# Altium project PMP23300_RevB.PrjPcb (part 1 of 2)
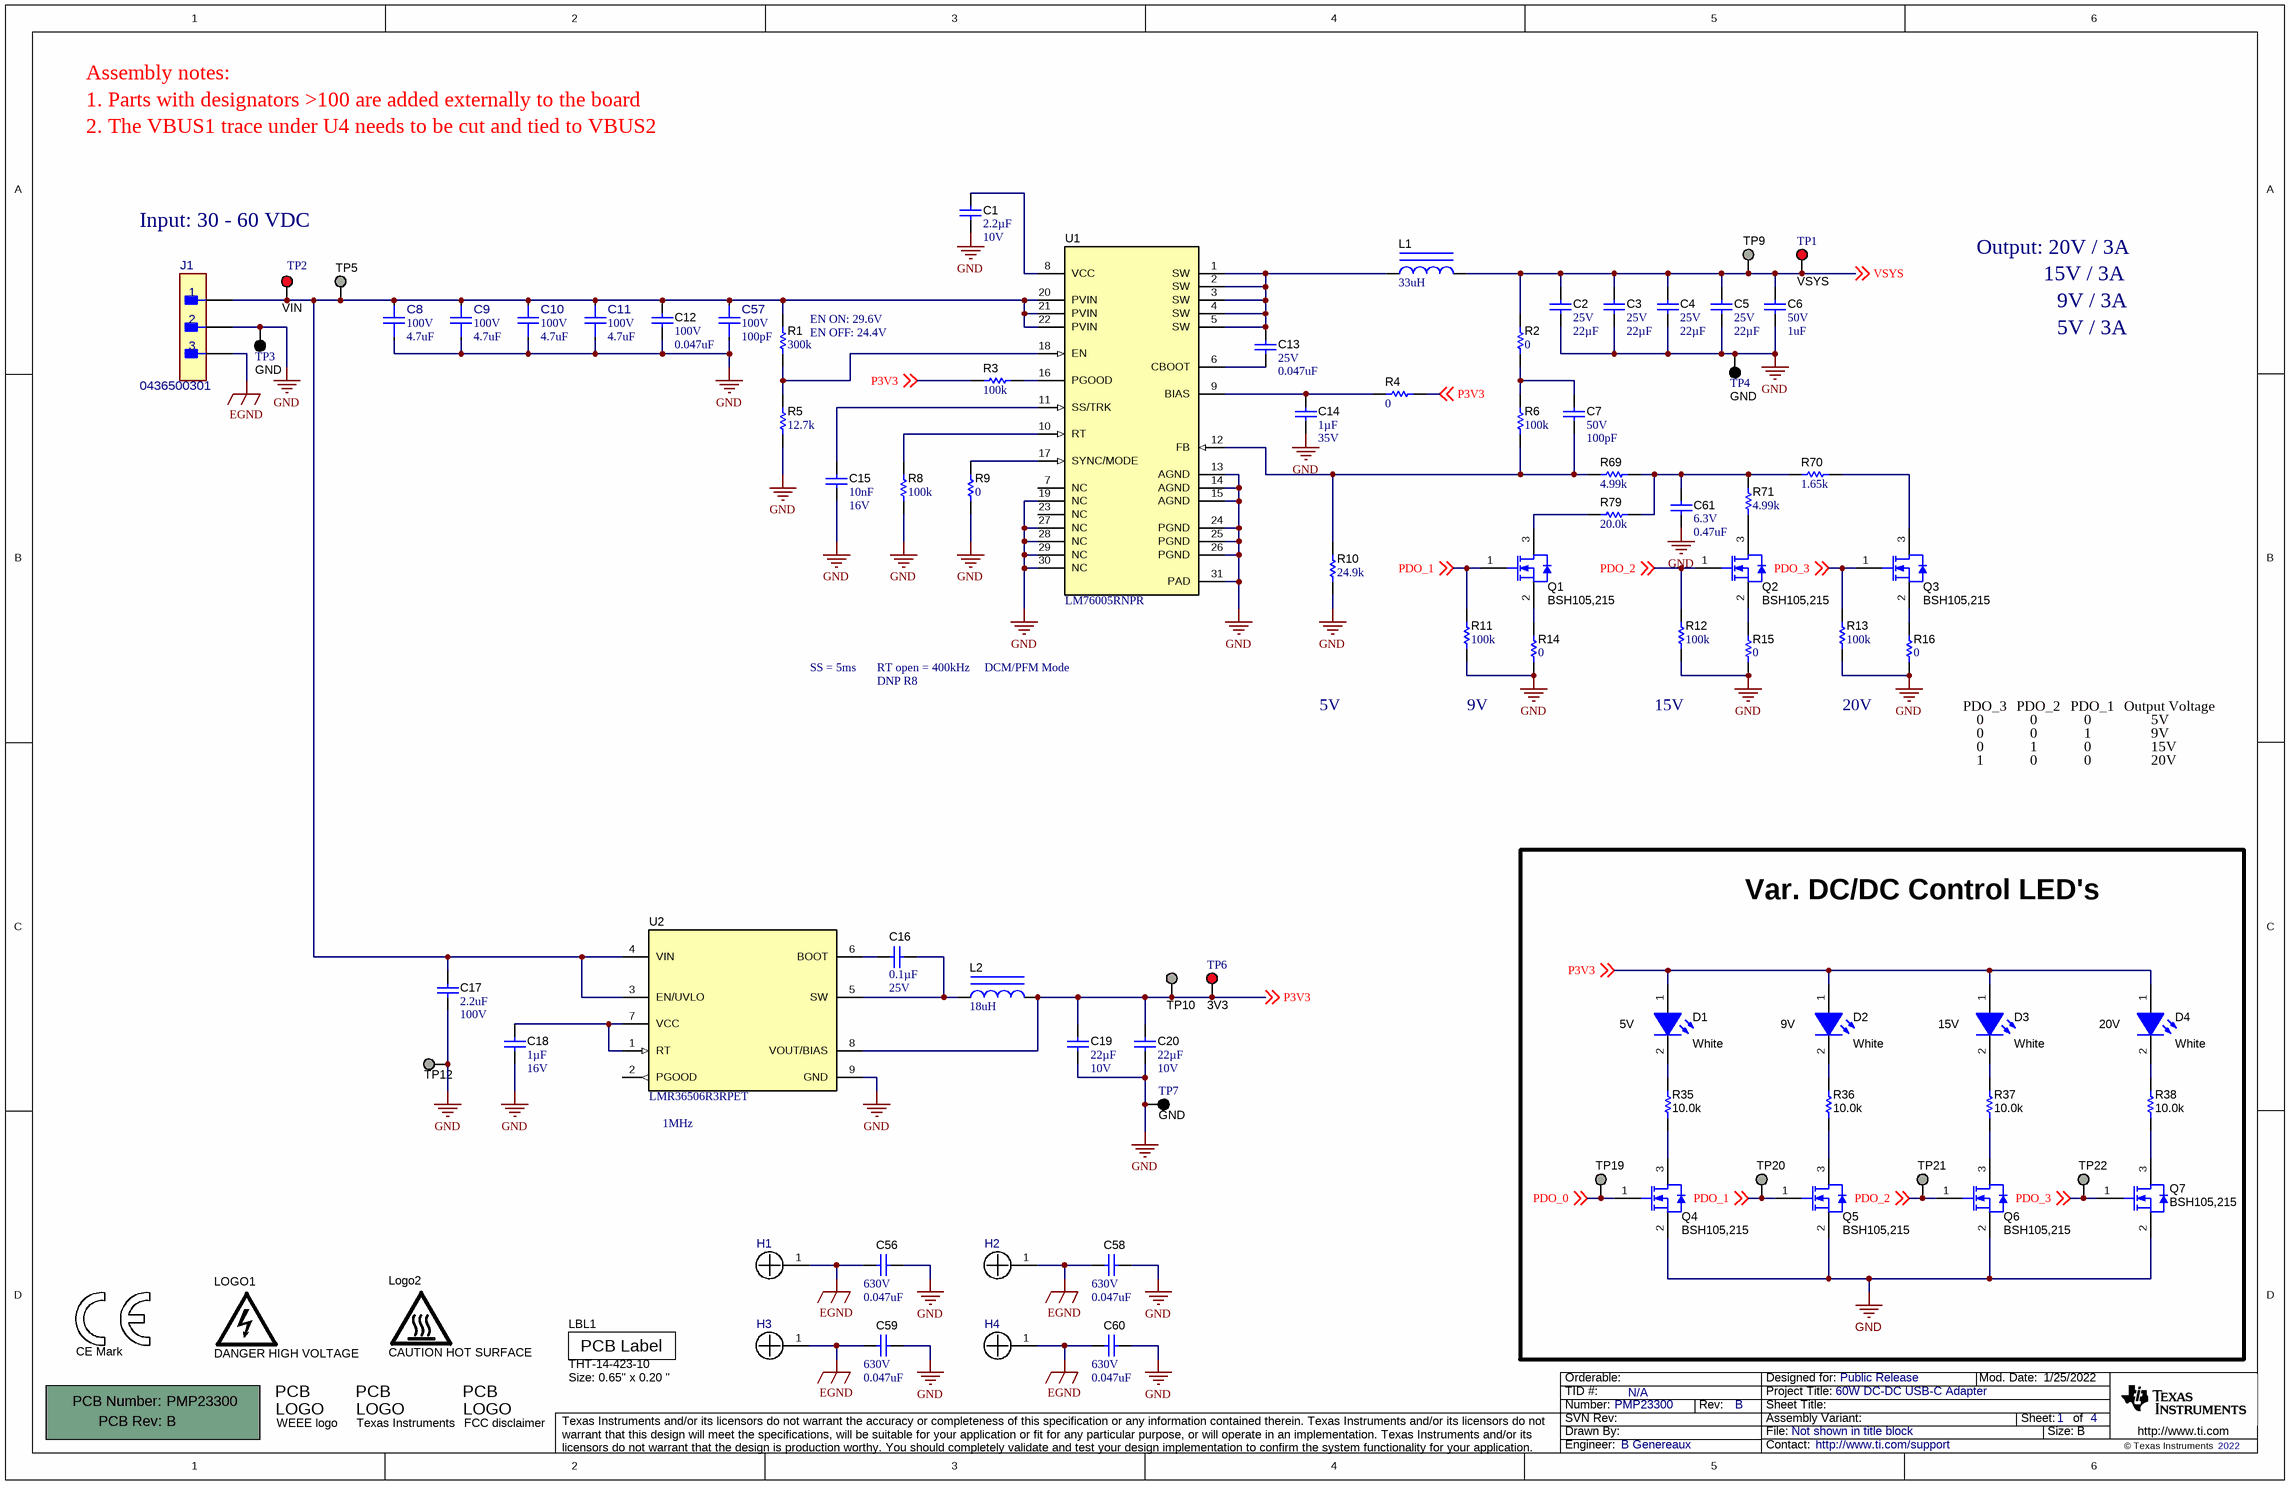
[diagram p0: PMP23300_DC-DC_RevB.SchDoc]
CopyrightYear: 2022; PCB_Rev: B; PRJ_Customer: Public Release; PRJ_Engineer: B Genereaux; PRJ_Number: PMP23300; PRJ_Title: 60W DC-DC USB-C Adapter; SCH_Rev: B; TechSupport: http://www.ti.com/support; TID: N/A
4 sheets, 204 parts. Net scope: global (net labels, ports and power ports of the same name join across sheets).
Board file: PMP23300_RevB.PcbDoc
Sheets:
  PMP23300_DC-DC_RevB.SchDoc
  PMP23300_PD_Control_RevB.SchDoc
  PMP23300_TIVA_RevB.SchDoc
  PMP23300_PD_Power_RevB.SchDoc

## Sheet PMP23300_DC-DC_RevB.SchDoc
size 431 x 279 mm; Date: Not shown in title block; ApprovedBy: Not shown in title block; CheckedBy: Not shown in title block; Author: Not shown in title block; CompanyName: Not shown in title block; Engineer: Not shown in title block; Organization: Not shown in title block; Address1: Not shown in title block; Address2: Not shown in title block; Address3: Not shown in title block; Address4: Not shown in title block; DocumentNumber: 1; Revision: Use project parameter SCH_Rev; SheetNumber: 1; SheetTotal: 4; PageSetup: Record=PageOptions¦CenterHorizontal=True¦CenterVertical=True¦PrintScale=1.00¦XCorrection=1.00¦YCorrection=1.00¦PrintKind=0¦BorderSize=5000000¦LeftOffset=0¦BottomOffset=0¦Orientation=2¦PaperLength=1000¦PaperWidth=1000¦Scale=100¦PaperSource=15¦PrintQuality=600¦MediaType=1¦DitherType=10¦PaperKind=Letter¦PrintScaleMode=1

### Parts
!PCB1  Printed Circuit Board  (value not drawn)  (mechanical)
C1  Cap_F: 2.2µF  VDC_V: 10V  [0603]  (hidden comment: GRM188R71A225KE15D)
C2  VDC_V: 25V  ValueDisplayed: 22µF  [1210_280]  (hidden comment: C1210C226K3RAC7800)
C3  VDC_V: 25V  ValueDisplayed: 22µF  [1210_280]  (hidden comment: C1210C226K3RAC7800)
C4  VDC_V: 25V  ValueDisplayed: 22µF  [1210_280]  (hidden comment: C1210C226K3RAC7800)
C5  VDC_V: 25V  ValueDisplayed: 22µF  [1210_280]  (hidden comment: C1210C226K3RAC7800)
C6  VDC_V: 50V  ValueDisplayed: 1uF  [0603]  (hidden comment: C1608X5R1H105K080AB)
C7  VDC_V: 50V  ValueDisplayed: 100pF  [0402]  (hidden comment: 04025A101FAT2A)
C8  VDC_V: 100V  ValueDisplayed: 4.7uF  [FP-CNC6P1X7R2A475K250AE_1210-MFG]  (hidden comment: CNC6P1X7R2A475K250AE)
C9  VDC_V: 100V  ValueDisplayed: 4.7uF  [FP-CNC6P1X7R2A475K250AE_1210-MFG]  (hidden comment: CNC6P1X7R2A475K250AE)
C10  VDC_V: 100V  ValueDisplayed: 4.7uF  [FP-CNC6P1X7R2A475K250AE_1210-MFG]  (hidden comment: CNC6P1X7R2A475K250AE)
C11  VDC_V: 100V  ValueDisplayed: 4.7uF  [FP-CNC6P1X7R2A475K250AE_1210-MFG]  (hidden comment: CNC6P1X7R2A475K250AE)
C12  VDC_V: 100V  ValueDisplayed: 0.047uF  [0603]  (hidden comment: C1608X7S2A473K080AB)
C13  VDC_V: 25V  ValueDisplayed: 0.047uF  [0402]  (hidden comment: GRM155R71E473KA88D)
C14  Cap_F: 1µF  VDC_V: 35V  [0603]  (hidden comment: C1608X7R1V105K080AC)
C15  Cap_F: 10nF  VDC_V: 16V  [0603]  (hidden comment: GRM188R71C103KA01D)
C16  ValueDisplayed: 0.1µF  VDC_V: 25V  [0402]  (hidden comment: CC0402KRX7R8BB104)
C17  ValueDisplayed: 2.2uF  VDC_V: 100V  [1206_190]  (hidden comment: GRM31CR72A225KA73L)
C18  Cap_F: 1µF  VDC_V: 16V  [0603]  (hidden comment: CL10B105KO8NFNC)
C19  Cap_F: 22µF  VDC_V: 10V  [0805_HV]  (hidden comment: GRM21BZ71A226ME15L)
C20  Cap_F: 22µF  VDC_V: 10V  [0805_HV]  (hidden comment: GRM21BZ71A226ME15L)
C56  VDC_V: 630V  ValueDisplayed: 0.047uF  [1206]
C57  VDC_V: 100V  Cap_F: 100pF  [FP-06031C101JAT2A_0603-MFG]  (hidden comment: 06031C101JAT2A)
C58  VDC_V: 630V  ValueDisplayed: 0.047uF  [1206]
C59  VDC_V: 630V  ValueDisplayed: 0.047uF  [1206]
C60  VDC_V: 630V  ValueDisplayed: 0.047uF  [1206]
C61  VDC_V: 6.3V  ValueDisplayed: 0.47uF  [0402]  (hidden comment: JMK105B7474KVHF)
D1  value White  [LW QH8G_White]  (hidden comment: LW QH8G-Q2S2-3K5L-1)
D2  value White  [LW QH8G_White]  (hidden comment: LW QH8G-Q2S2-3K5L-1)
D3  value White  [LW QH8G_White]  (hidden comment: LW QH8G-Q2S2-3K5L-1)
D4  value White  [LW QH8G_White]  (hidden comment: LW QH8G-Q2S2-3K5L-1)
H1  NY PMS 440 0025 PH  [NY PMS 440 0025 PH]  (value not drawn)
H2  NY PMS 440 0025 PH  [NY PMS 440 0025 PH]  (value not drawn)
H3  NY PMS 440 0025 PH  [NY PMS 440 0025 PH]  (value not drawn)
H4  NY PMS 440 0025 PH  [NY PMS 440 0025 PH]  (value not drawn)
J1  0436500301  [FP-0436500301_CONN_HDR3-MFG]
L1  ValueDisplayed: 33uH  [WE-PD_1210]  (hidden comment: 7447709330)
L2  ValueDisplayed: 18uH  [WE-TPC-LH]  (hidden comment: 744053180)
LBL1  THT-14-423-10  Note: Size: 0.65" x 0.20 "  [Label_650x200]
LOGO1  DANGER HIGH VOLTAGE  [IEC_HighVoltage_Small]  (no BOM)
Logo2  CAUTION HOT SURFACE  [IEC_HotSurface_Small]  (no BOM)
Logo3  CE Mark  [CE_Mark_5mm]  (no BOM)
Logo4  WEEE logo  [WEEE_Minimum]  (no BOM)
Logo5  Texas Instruments  [TI_Stacked_Overlay_Small]  (no BOM)
Logo6  FCC disclaimer  [FCC_disclaimer]  (no BOM)
Q1  BSH105,215  [SOT-23]
Q2  BSH105,215  [SOT-23]
Q3  BSH105,215  [SOT-23]
Q4  BSH105,215  [SOT-23]
Q5  BSH105,215  [SOT-23]
Q6  BSH105,215  [SOT-23]
Q7  BSH105,215  [SOT-23]
R1  ValueDisplayed: 300k  [0402]  (hidden comment: CRCW0402300KFKED)
R2  ValueDisplayed: 0  [0402]  (hidden comment: CRCW04020000Z0EDHP)
R3  ValueDisplayed: 100k  [0402]  (hidden comment: RC1005F104CS)
R4  ValueDisplayed: 0  [0402]  (hidden comment: CRCW04020000Z0EDHP)
R5  ValueDisplayed: 12.7k  [0402]  (hidden comment: CRCW040212K7FKED)
R6  ValueDisplayed: 100k  [0402]  (hidden comment: RC1005F104CS)
R8  ValueDisplayed: 100k  [0402]  (hidden comment: RC1005F104CS)
R9  ValueDisplayed: 0  [0402]  (hidden comment: CRCW04020000Z0EDHP)
R10  ValueDisplayed: 24.9k  [0402]  (hidden comment: CRCW040224K9FKED)
R11  ValueDisplayed: 100k  [0402]  (hidden comment: RC1005F104CS)
R12  ValueDisplayed: 100k  [0402]  (hidden comment: RC1005F104CS)
R13  ValueDisplayed: 100k  [0402]  (hidden comment: RC1005F104CS)
R14  ValueDisplayed: 0  [0402]  (hidden comment: CRCW04020000Z0EDHP)
R15  ValueDisplayed: 0  [0402]  (hidden comment: CRCW04020000Z0EDHP)
R16  ValueDisplayed: 0  [0402]  (hidden comment: CRCW04020000Z0EDHP)
R35  ValueDisplayed: 10.0k  [0402]  (hidden comment: ERJ-2RKF1002X)
R36  ValueDisplayed: 10.0k  [0402]  (hidden comment: ERJ-2RKF1002X)
R37  ValueDisplayed: 10.0k  [0402]  (hidden comment: ERJ-2RKF1002X)
R38  ValueDisplayed: 10.0k  [0402]  (hidden comment: ERJ-2RKF1002X)
R69  ValueDisplayed: 4.99k  [0402]  (hidden comment: RC0402FR-074K99L)
R70  ValueDisplayed: 1.65k  [0402]  (hidden comment: CRCW04021K65FKED)
R71  ValueDisplayed: 4.99k  [0402]  (hidden comment: RC0402FR-074K99L)
R79  ValueDisplayed: 20.0k  [0402]  (hidden comment: CRCW040220K0FKED)
TP1  VSYS  [Keystone5010]
TP2  VIN  [Keystone5010]
TP3  GND  [Keystone5011]
TP4  GND  [Keystone5011]
TP5  S1751-46  [Harwin_S1751-46]  (value not drawn)
TP6  3V3  [Keystone5010]
TP7  GND  [Keystone5011]
TP9  S1751-46  [Harwin_S1751-46]  (value not drawn)
TP10  S1751-46  [Harwin_S1751-46]  (value not drawn)
TP12  S1751-46  [Harwin_S1751-46]  (value not drawn)
TP19  S1751-46  [Harwin_S1751-46]  (value not drawn)
TP20  S1751-46  [Harwin_S1751-46]  (value not drawn)
TP21  S1751-46  [Harwin_S1751-46]  (value not drawn)
TP22  S1751-46  [Harwin_S1751-46]  (value not drawn)
U1  LM76005RNPR  [RNP0030A]
U2  LMR36506R3RPET  [RPE0009A]

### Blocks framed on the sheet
Var. DC/DC Control LED's: D1-D4 Q4-Q7 R35-R38 TP19-TP22

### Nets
EGND: C56.2 C58.2 C59.2 C60.2 H1.1 H2.1 H3.1 H4.1 J1.3
GND: C1.2 C2.2 C3.2 C4.2 C5.2 C6.2 C8.1 C9.1 C10.1 C11.1 C12.2 C14.2 C15.2 C17.2 C18.2 C19.2 C20.2 C56.1 C57.1 C58.1 C59.1 C60.1 C61.2 J1.2 Q4.2(S) Q5.2(S) Q6.2(S) Q7.2(S) R5.1 R8.1 R9.2 R10.1 R11.1 R12.1 R13.1 R14.2 R15.2 R16.2 TP3.1 TP4.1 TP7.1 TP12.1 U1.13(AGND) U1.14(AGND) U1.15(AGND) U1.19(NC) U1.24(PGND) U1.25(PGND) U1.26(PGND) U1.27(NC) U1.28(NC) U1.29(NC) U1.30(NC) U1.31(PAD) U2.9(GND)
P3V3: C19.1 C20.1 D1.1(A) D2.1(A) D3.1(A) D4.1(A) L2.2 R3.1 R4.1 TP6.1 TP10.1 U2.8(VOUT/BIAS) ; off-sheet P3V3
PDO_0: Q4.1(G) TP19.1 ; off-sheet PDO_0
PDO_1: Q1.1(G) Q5.1(G) R11.2 TP20.1 ; off-sheet PDO_1
PDO_2: Q2.1(G) Q6.1(G) R12.2 TP21.1 ; off-sheet PDO_2
PDO_3: Q3.1(G) Q7.1(G) R13.2 TP22.1 ; off-sheet PDO_3
VSYS: C2.1 C3.1 C4.1 C5.1 C6.1 L1.2 R2.1 TP1.1 TP9.1 ; off-sheet VSYS
NetC1_1: C1.1 U1.8(VCC)
NetC7_1: C7.1 R2.2 R6.2
NetC7_2: C7.2 R6.1 R10.2 R69.1 U1.12(FB)
NetC8_2: C8.2 C9.2 C10.2 C11.2 C12.1 C17.1 C57.2 J1.1 R1.2 TP2.1 TP5.1 U1.20(PVIN) U1.21(PVIN) U1.22(PVIN) U2.3(EN/UVLO) U2.4(VIN)
NetC13_1: C13.1 L1.1 U1.1(SW) U1.2(SW) U1.3(SW) U1.4(SW) U1.5(SW)
NetC13_2: C13.2 U1.6(CBOOT)
NetC14_1: C14.1 R4.2 U1.9(BIAS)
NetC15_1: C15.1 U1.11(SS/TRK)
NetC16_1: C16.1 L2.1 U2.5(SW)
NetC16_2: C16.2 U2.6(BOOT)
NetC18_1: C18.1 U2.1(RT) U2.7(VCC)
NetC61_1: C61.1 R69.2 R70.1 R71.2 R79.2
NetD1_2: D1.2(K) R35.2
NetD2_2: D2.2(K) R36.2
NetD3_2: D3.2(K) R37.2
NetD4_2: D4.2(K) R38.2
NetQ1_2: Q1.2(S) R14.1
NetQ1_3: Q1.3(D) R79.1
NetQ2_2: Q2.2(S) R15.1
NetQ2_3: Q2.3(D) R71.1
NetQ3_2: Q3.2(S) R16.1
NetQ3_3: Q3.3(D) R70.2
NetQ4_3: Q4.3(D) R35.1
NetQ5_3: Q5.3(D) R36.1
NetQ6_3: Q6.3(D) R37.1
NetQ7_3: Q7.3(D) R38.1
NetR1_1: R1.1 R5.2 U1.18(EN)
NetR3_2: R3.2 U1.16(PGOOD)
NetR8_2: R8.2 U1.10(RT)
NetR9_1: R9.1 U1.17(SYNC/MODE)

Not connected (* = marked no-connect by the designer): U1 7(NC) 23(NC); U2 2(PGOOD)

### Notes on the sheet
- Assembly notes:
- 1. Parts with designators >100 are added externally to the board
- 2. The VBUS1 trace under U4 needs to be cut and tied to VBUS2
- Input: 30 - 60 VDC
- Output: 20V / 3A
- 15V / 3A
- (near R1) EN ON: 29.6V
- (near R1) EN OFF: 24.4V
- 9V / 3A
- 5V / 3A
- SS = 5ms
- RT open = 400kHz
- DNP R8
- DCM/PFM Mode
- 5V
- 9V
- (near R12) 15V
- 20V
- PDO_3
- 0
- 1
- PDO_2
- PDO_1
- Output Voltage
- 15V
- (near D1) 5V
- (near D2) 9V
- (near D3) 15V
- (near D4) 20V
- (near U2) 1MHz

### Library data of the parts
!PCB1 = CMP-0003618-2: Manufacturer: Any; PartNumber: PMP23300
C1 = CMP-0007370-4: CAP, CERM, 2.2 uF, 10 V, +/- 10%, X7R, 0603; Manufacturer: MuRata; TaMin_C: -55°C; ESR_ohm: 9m; Polarized: N; SizeAreaWB_mm2: 4.68; Value1: 0.009 ohm; U/M: EA; Value: 2.2uF; TaMax_C: 125°C; SizeZ_mm: 1; SizeX_mm: 1.6; SizeY_mm: 0.8; SizeArea_mm2: 1.28; AEC Category: Q200
C2-C5 = CMP-0082266-1: CAP, CERM, 22 µF, 25 V,+/- 10%, X7R, 1210; Manufacturer: Kemet; TaMin_C: -55°C; ESR_ohm: 1m; Polarized: N; Green_Lifecycle: Active; SizeAreaWB_mm2: 14.7; Green_REACh: Incomplete; Value1: 0.001 ohm; U/M: EA; Value: 22uF; TaMax_C: 125°C; SizeZ_mm: 2.8; SizeX_mm: 3.2; SizeY_mm: 2.5; Cap_Case: 1210; SizeArea_mm2: 8; AEC Category: Q200
C6 = CMP-0007011-5: CAP, CERM, 1 uF, 50 V, +/- 10%, X5R, 0603; Manufacturer: TDK; TaMin_C: -55°C; ESR_ohm: 5.522m; Polarized: N; SizeAreaWB_mm2: 4.68; Value1: 0.005522 ohm; U/M: EA; Value: 1uF; TaMax_C: 85°C; SizeZ_mm: 1; SizeX_mm: 1.6; SizeY_mm: 0.8; SizeArea_mm2: 1.28; Cap_F: 1µF; IRMS_A: 2.2162A; AEC Category: Q200
C7 = CMP-0006196-2: CAP, CERM, 100 pF, 50 V, +/- 1%, C0G/NP0, 0402; Manufacturer: AVX; TaMin_C: -55°C; Polarized: N; SizeAreaWB_mm2: 3; Value1: Unknown; U/M: EA; Value: 100pF; TaMax_C: 125°C; SizeZ_mm: 0.6; SizeX_mm: 1; SizeY_mm: 0.5; AEC Category: Q200
C8-C11 = CMP-0094503-1: 4.7 µF ±10% 100V Ceramic Capacitor X7R 1210 (3225 Metric); Manufacturer: TDK; AEC Qualified: No; TempCo: 15%; SizeZ_mm: 2.8mm; Value: 4.7µF
C12 = CMP-0007060-4: CAP, CERM, 0.047 uF, 100 V, +/- 10%, X7S, 0603; Manufacturer: TDK; TaMin_C: -55°C; ESR_ohm: 89.796m; Polarized: N; SizeAreaWB_mm2: 4.68; Value1: 0.089796 ohm; U/M: EA; TaMax_C: 125°C; SizeZ_mm: 1; SizeX_mm: 1.6; SizeY_mm: 0.8; SizeArea_mm2: 1.28; Cap_F: 47nF; IRMS_A: 567.484mA; AEC Category: Q200
C13 = CMP-0006669-2: CAP, CERM, 0.047 uF, 25 V, +/- 10%, X7R, 0402; Manufacturer: MuRata; TaMin_C: -55°C; Polarized: N; SizeAreaWB_mm2: 3; Value1: Unknown; U/M: EA; TaMax_C: 125°C; SizeZ_mm: 0.6; SizeX_mm: 1; SizeY_mm: 0.5; Cap_F: 47nF; AEC Category: Q200
C14 = CMP-0007052-4: CAP, CERM, 1 uF, 35 V, +/- 10%, X7R, 0603; Manufacturer: TDK; TaMin_C: -55°C; Polarized: N; SizeAreaWB_mm2: 4.68; Value1: Unknown; U/M: EA; Value: 1uF; TaMax_C: 125°C; SizeZ_mm: 1; SizeX_mm: 1.6; SizeY_mm: 0.8; SizeArea_mm2: 1.28; AEC Category: Q200
C15 = CMP-0007377-4: CAP, CERM, 0.01 uF, 16 V, +/- 10%, X7R, 0603; Manufacturer: MuRata; TaMin_C: -55°C; Polarized: N; SizeAreaWB_mm2: 4.68; Value1: Unknown; U/M: EA; Value: 0.01uF; TaMax_C: 125°C; SizeZ_mm: 1; SizeX_mm: 1.6; SizeArea_mm2: 1.28; AEC Category: Q200; SizeY_mm: 0.8
C16 = CMP-0860555-1: CAP, CERM, 0.1 µF, 25 V,+/- 10%, X7R, 0402; Manufacturer: Yageo; SizeArea_mm2: 0.5; AEC Qualified: N; SizeX_mm: 1; U/M: EA; Value: 0.1uF; TaMin_C: -55°C; SizeZ_mm: 0.6; Cap_F: 100nF; TaMax_C: 125°C; SizeAreaWB_mm2: 3; AEC Category: Q200
C17 = CMP-0008971-3: CAP, CERM, 2.2 uF, 100 V, +/- 10%, X7R, 1206_190; Manufacturer: MuRata; SizeY_mm: 1.6; AEC Category: Q200; Value1: Unknown; U/M: EA; SizeZ_mm: 1.9; Polarized: N; MFG_Status: TI_Obsolete; SizeArea_mm2: 5.12; Value: 2.2uF; TaMax_C: 125°C; Cap_F: 2.2µF; TaMin_C: -55°C; SizeX_mm: 3.2; Cap_Case: 1206; SizeAreaWB_mm2: 10.92
C18 = CMP-0085537-1: CAP, CERM, 1 µF, 16 V,+/- 10%, X7R, 0603; Manufacturer: Samsung Electro-Mechanics; SizeZ_mm: 1; SizeY_mm: 0.8; TaMin_C: -55°C; AEC Qualified: N; U/M: EA; AEC Category: Q200; SizeAreaWB_mm2: 4.68; TaMax_C: 125°C; SizeX_mm: 1.6; Value: 1uF; SizeArea_mm2: 1.28
C19 C20 = CMP-0008377-2: CAP, CERM, 22 uF, 10 V, +/- 20%, X7R, 0805; Manufacturer: MuRata; SizeY_mm: 1.25; Cap_Case: 0805; SizeArea_mm2: 2.5; AEC Qualified: N; AEC Category: Q200; ValueDisplayed: 22uF; TaMin_C: -55°C; SizeAreaWB_mm2: 6.75; Value1: Unknown; U/M: EA; Value: 22uF; TaMax_C: 125°C; SizeZ_mm: 1.45; SizeX_mm: 2
C56 C58-C60 = CMP-0009060-2: CAP, CERM, 0.047 uF, 630 V, +/- 10%, X7T, 1206; TaMin_C: -55°C; Polarized: N; SizeAreaWB_mm2: 10.92; Value1: Unknown; U/M: EA; TaMax_C: 125°C; SizeZ_mm: 1.35; SizeX_mm: 3.2; SizeY_mm: 1.6; SizeArea_mm2: 5.12; Cap_F: 47nF
C57 = CMP-0096605-1: 100 pF ±5% 100V Ceramic Capacitor X7R 0603 (1608 Metric); Manufacturer: KYOCERA AVX; TempCo: 15%; AEC Qualified: No; SizeZ_mm: 0.9mm; Value: 100pF
C61 = CMP-0006717-2: CAP, CERM, 0.47 uF, 6.3 V, +/- 10%, X7R, 0402; Manufacturer: Taiyo Yuden; TaMin_C: -55°C; Polarized: N; SizeAreaWB_mm2: 3; Value1: Unknown; U/M: EA; Value: 0.47uF; TaMax_C: 125°C; SizeZ_mm: 0.6; SizeX_mm: 1; SizeY_mm: 0.5; Cap_F: 470nF; AEC Category: Q200
D1-D4 = CMP-0002919-1: LED, White, SMD; Manufacturer: OSRAM; Vf_V: 2.8V; Io_A: 5mA; Vr_V: 5V; Ir_A: 10nA; Tjmax_C: 95°C; Value1: W; Angle: 120; U/M: EA
H1-H4 = CMP-0003617-1: Machine Screw, Round, #4-40 x 1/4, Nylon, Philips panhead; Manufacturer: B&F Fastener Supply; CompType: Hardware
J1 = CMP-0096579-1: Conn Power HDR 3 POS 3mm Solder RA Thru-Hole 3 Terminal 1 Port Micro-Fit 3.0™ Frame; Manufacturer: Molex; ContactFinish: Gold,Nickel; Current_A: 8.5A; AEC Qualified: No; Conn Gender: Male; SizeZ_mm: 6.07mm; Voltage_V: 600V; Row_Count: 1; Conn Orientation: Right Angle
L1 = CMP-0064540-1: Inductor, Shielded Drum Core, Ferrite, 33 uH, 4.2 A, 0.0368 ohm, SMD; Manufacturer: Wurth Elektronik; Isat: 5.5A @ 10% inductance drop; Irms: 4.2A @ 40C rise; Green_Lifecycle: Active; SizeAreaWB_mm2: 196; DCR_ohm: 36.8m; Green_REACh: Passed; Value: 33uH; Imax_A: 4.2A; SizeZ_mm: 10; SizeX_mm: 12; SizeArea_mm2: 144; Ind_H: 33µH; AEC Category: Q200
L2 = CMP-0064421-1: Inductor, Shielded Drum Core, Ferrite, 18 uH, 1.1 A, 0.088 ohm, SMD; Manufacturer: Wurth Elektronik; Isat: 1.1A @ 35% inductance drop; Irms: 1.25A @ 30C rise; Green_Lifecycle: Active; SizeAreaWB_mm2: 60.84; DCR_ohm: 88m; Green_REACh: Passed; Value: 18uH; Imax_A: 1.1A; SizeZ_mm: 2.8; SizeX_mm: 5.8; SizeArea_mm2: 33.64; Ind_H: 18µH; AEC Category: Q200
LBL1 = CMP-0003625-1: Thermal Transfer Printable Labels, 0.650" W x 0.200" H - 10,000 per roll; Manufacturer: Brady; CompType: Label
LOGO1 = CMP-0074835-1: IEC 61010-1 High Voltage Warning; SymbolCreator: a0412235
Logo2 = CMP-0074837-2: IEC 61010-1 Hot Surface Warning; Manufacturer: Texas Instruments; CompType: IC; AEC Category: Q200; SymbolCreator: a0412235
Logo3 = CMP-0074844-1: SymbolCreator: a0412235
Logo4 = CMP-0074769-1
Logo5 = CMP-0074838-1: Texas Instrument Corporate Signature; SymbolCreator: a0412235; Lib Reference: TI_Logo; Library Reference: Logo
Logo6 = CMP-0074847-1: FCC_disclaimer; Library Reference: Logo
Q1-Q7 = CMP-0000205-2: MOSFET, N-CH, 20 V, 1.05 A, SOT-23; Alternate Manufacturer: None; Manufacturer: Nexperia; SizeZ_mm: 1.1; ChType: N; Value2: 3.9 nC; Value1: 0; VdsMax_V: 20V; SizeX_mm: 2.5; SizeY_mm: 3; Vgs_V: 8V; Value: 20V; Rdson45_ohm: 0.2; SizeArea_mm2: 7.5; AEC Category: Q101; IdsMax_A: 1.05A; SizeAreaWB_mm2: 14; QgTyp_nC: 3.9
R1 = CMP-0026279-2: RES, 300 k, 1%, 0.063 W, AEC-Q200 Grade 0, 0402; Manufacturer: Vishay-Dale; Power_W: 63mW; TempCo: 100 ppm/C; Value: 300k; SizeX_mm: 1; SizeY_mm: 0.5; SizeZ_mm: 0.6; Value2: 0.063W; AEC Qualified: Y; VDC_V: 50V; AEC Grade: 0; AEC Category: Q200
R2 R4 R9 R14-R16 = CMP-0081856-1: RES, 0, 0%, 0.2 W, AEC-Q200 Grade 0, 0402; Manufacturer: Vishay-Dale; SizeAreaWB_mm2: 3; SizeArea_mm2: 0.5; AEC Qualified: Y; AEC Category: Q200; Value: 0; SizeZ_mm: 0.6; Power_W: 200mW; VDC_V: 50V; Value2: 0.2W; SizeX_mm: 1
R3 R6 R8 R11-R13 = CMP-0026745-1: RES, 100 k, 1%, 0.063 W, 0402; Manufacturer: Samsung Electro-Mechanics; Power_W: 63mW; TempCo: 100 ppm/C; U/M: EA; Value: 100k; EIA_Code: E96; SizeX_mm: 1; SizeY_mm: 0.5; SizeZ_mm: 0.6; Value2: 0.063W; AEC Qualified: N; VDC_V: 80V; AEC Category: Q200
R5 = CMP-0025993-3: RES, 12.7 k, 1%, 0.063 W, AEC-Q200 Grade 0, 0402; Manufacturer: Vishay-Dale; Power_W: 63mW; TempCo: 100 ppm/C; Value_Code: 12k7; Value: 12.7k; EIA_Code: E96; SizeX_mm: 1; SizeY_mm: 0.5; SizeZ_mm: 0.6; Value2: 0.063W; AEC Qualified: Y; VDC_V: 50V; AEC Category: Q200; AEC Grade: 0
R10 = CMP-0026196-2: RES, 24.9 k, 1%, 0.063 W, AEC-Q200 Grade 0, 0402; Manufacturer: Vishay-Dale; Power_W: 63mW; TempCo: 100 ppm/C; Value_Code: 24k9; Value: 24.9k; EIA_Code: E96; SizeX_mm: 1; SizeY_mm: 0.5; SizeZ_mm: 0.6; Value2: 0.063W; AEC Qualified: Y; VDC_V: 50V; AEC Category: Q200; AEC Grade: 0
R35-R38 = CMP-0026658-1: RES, 10.0 k, 1%, 0.1 W, 0402; Manufacturer: Panasonic; Value: 10.0k; Res_ohm: 10k; Value_Code: 10k0; Power_W: 100mW; Value2: 0.1W; VDC_V: 50V; TempCo: 100 ppm/C; SizeArea_mm2: 0.5; SizeX_mm: 1; SizeZ_mm: 0.6; EIA_Code: E96; U/M: EA; AEC Category: Q200
R69 R71 = CMP-0026740-1: RES, 4.99 k, 1%, 0.063 W, 0402; Manufacturer: Yageo America; Power_W: 63mW; TempCo: 100 ppm/C; Value_Code: 4k99; U/M: EA; Value: 4.99k; EIA_Code: E96; SizeX_mm: 1; SizeY_mm: 0.5; SizeZ_mm: 0.6; Value2: 0.063W; AEC Qualified: N; VDC_V: 50V; AEC Category: Q200
R70 = CMP-0026092-3: RES, 1.65 k, 1%, 0.063 W, AEC-Q200 Grade 0, 0402; Manufacturer: Vishay-Dale; Power_W: 63mW; TempCo: 100 ppm/C; Value_Code: 1k65; Value: 1.65k; EIA_Code: E96; SizeX_mm: 1; SizeY_mm: 0.5; SizeZ_mm: 0.6; Value2: 0.063W; AEC Qualified: Y; VDC_V: 50V; AEC Category: Q200; AEC Grade: 0
R79 = CMP-0026162-2: RES, 20.0 k, 1%, 0.063 W, AEC-Q200 Grade 0, 0402; Manufacturer: Vishay-Dale; Power_W: 63mW; TempCo: 100 ppm/C; Value_Code: 20k0; Value: 20.0k; EIA_Code: E96; Res_ohm: 20k; SizeX_mm: 1; SizeY_mm: 0.5; SizeZ_mm: 0.6; Value2: 0.063W; AEC Qualified: Y; VDC_V: 50V; AEC Category: Q200; AEC Grade: 0
TP1 TP2 TP6 = CMP-0055147-2: Test Point, Multipurpose, Red, TH; Manufacturer: Keystone Electronics; CT: TRUE; ContactFinish: Silver; Green_Lifecycle: Active; CNHeader: FALSE; Green_REACh: Passed
TP3 TP4 TP7 = CMP-0055148-2: Test Point, Multipurpose, Black, TH; Manufacturer: Keystone Electronics; CNHeader: FALSE; ContactFinish: Silver; Green_REACh: Passed; Green_Lifecycle: Active; CT: TRUE
TP5 TP9 TP10 TP12 TP19-TP22 = CMP-0075188-1: Test Lead clips and hooks, SMT; Manufacturer: Harwin; CNHeader: False; Current_A: 2A; CompType: Test Point; ContactFinish: Tin; CT: True
U1 = CMP-0861019-1: 3.5V to 60V 5A Synchronous Step-Down Voltage Regulator, RNP0030A (WQFN-30); Alternate Manufacturer: Texas Instruments; AEC Category: Q200; SizeArea_mm2: 24; SizeX_mm: 4; SizeZ_mm: 0.8; AEC Qualified: N; SizeAreaWB_mm2: 48; SizeY_mm: 6; CompType: IC
U2 = CMP-0750092-1: LMR36503/06-Q1 Wide Input 60-V Synchronous, DC-DC Buck Converter, RPE0009A (VQFN-9); Alternate PartNumber: LMR36506R3RPER; Alternate Manufacturer: Texas Instruments; AEC Category: Q200; SizeZ_mm: 1; SizeAreaWB_mm2: 9; AEC Qualified: N; CompType: IC; SizeY_mm: 2; SizeArea_mm2: 4

## Sheet PMP23300_PD_Control_RevB.SchDoc
size 431 x 279 mm; Date: Not shown in title block; ApprovedBy: Not shown in title block; CheckedBy: Not shown in title block; Author: Not shown in title block; CompanyName: Not shown in title block; Engineer: Not shown in title block; Organization: Not shown in title block; Address1: Not shown in title block; Address2: Not shown in title block; Address3: Not shown in title block; Address4: Not shown in title block; DocumentNumber: 3; Revision: Use project parameter SCH_Rev; SheetNumber: 3; SheetTotal: 4; PageSetup: Record=PageOptions¦CenterHorizontal=True¦CenterVertical=True¦PrintScale=1.00¦XCorrection=1.00¦YCorrection=1.00¦PrintKind=0¦BorderSize=5000000¦LeftOffset=0¦BottomOffset=0¦Orientation=2¦PaperLength=1000¦PaperWidth=1000¦Scale=100¦PaperSource=15¦PrintQuality=600¦MediaType=1¦DitherType=10¦PaperKind=Letter¦PrintScaleMode=1
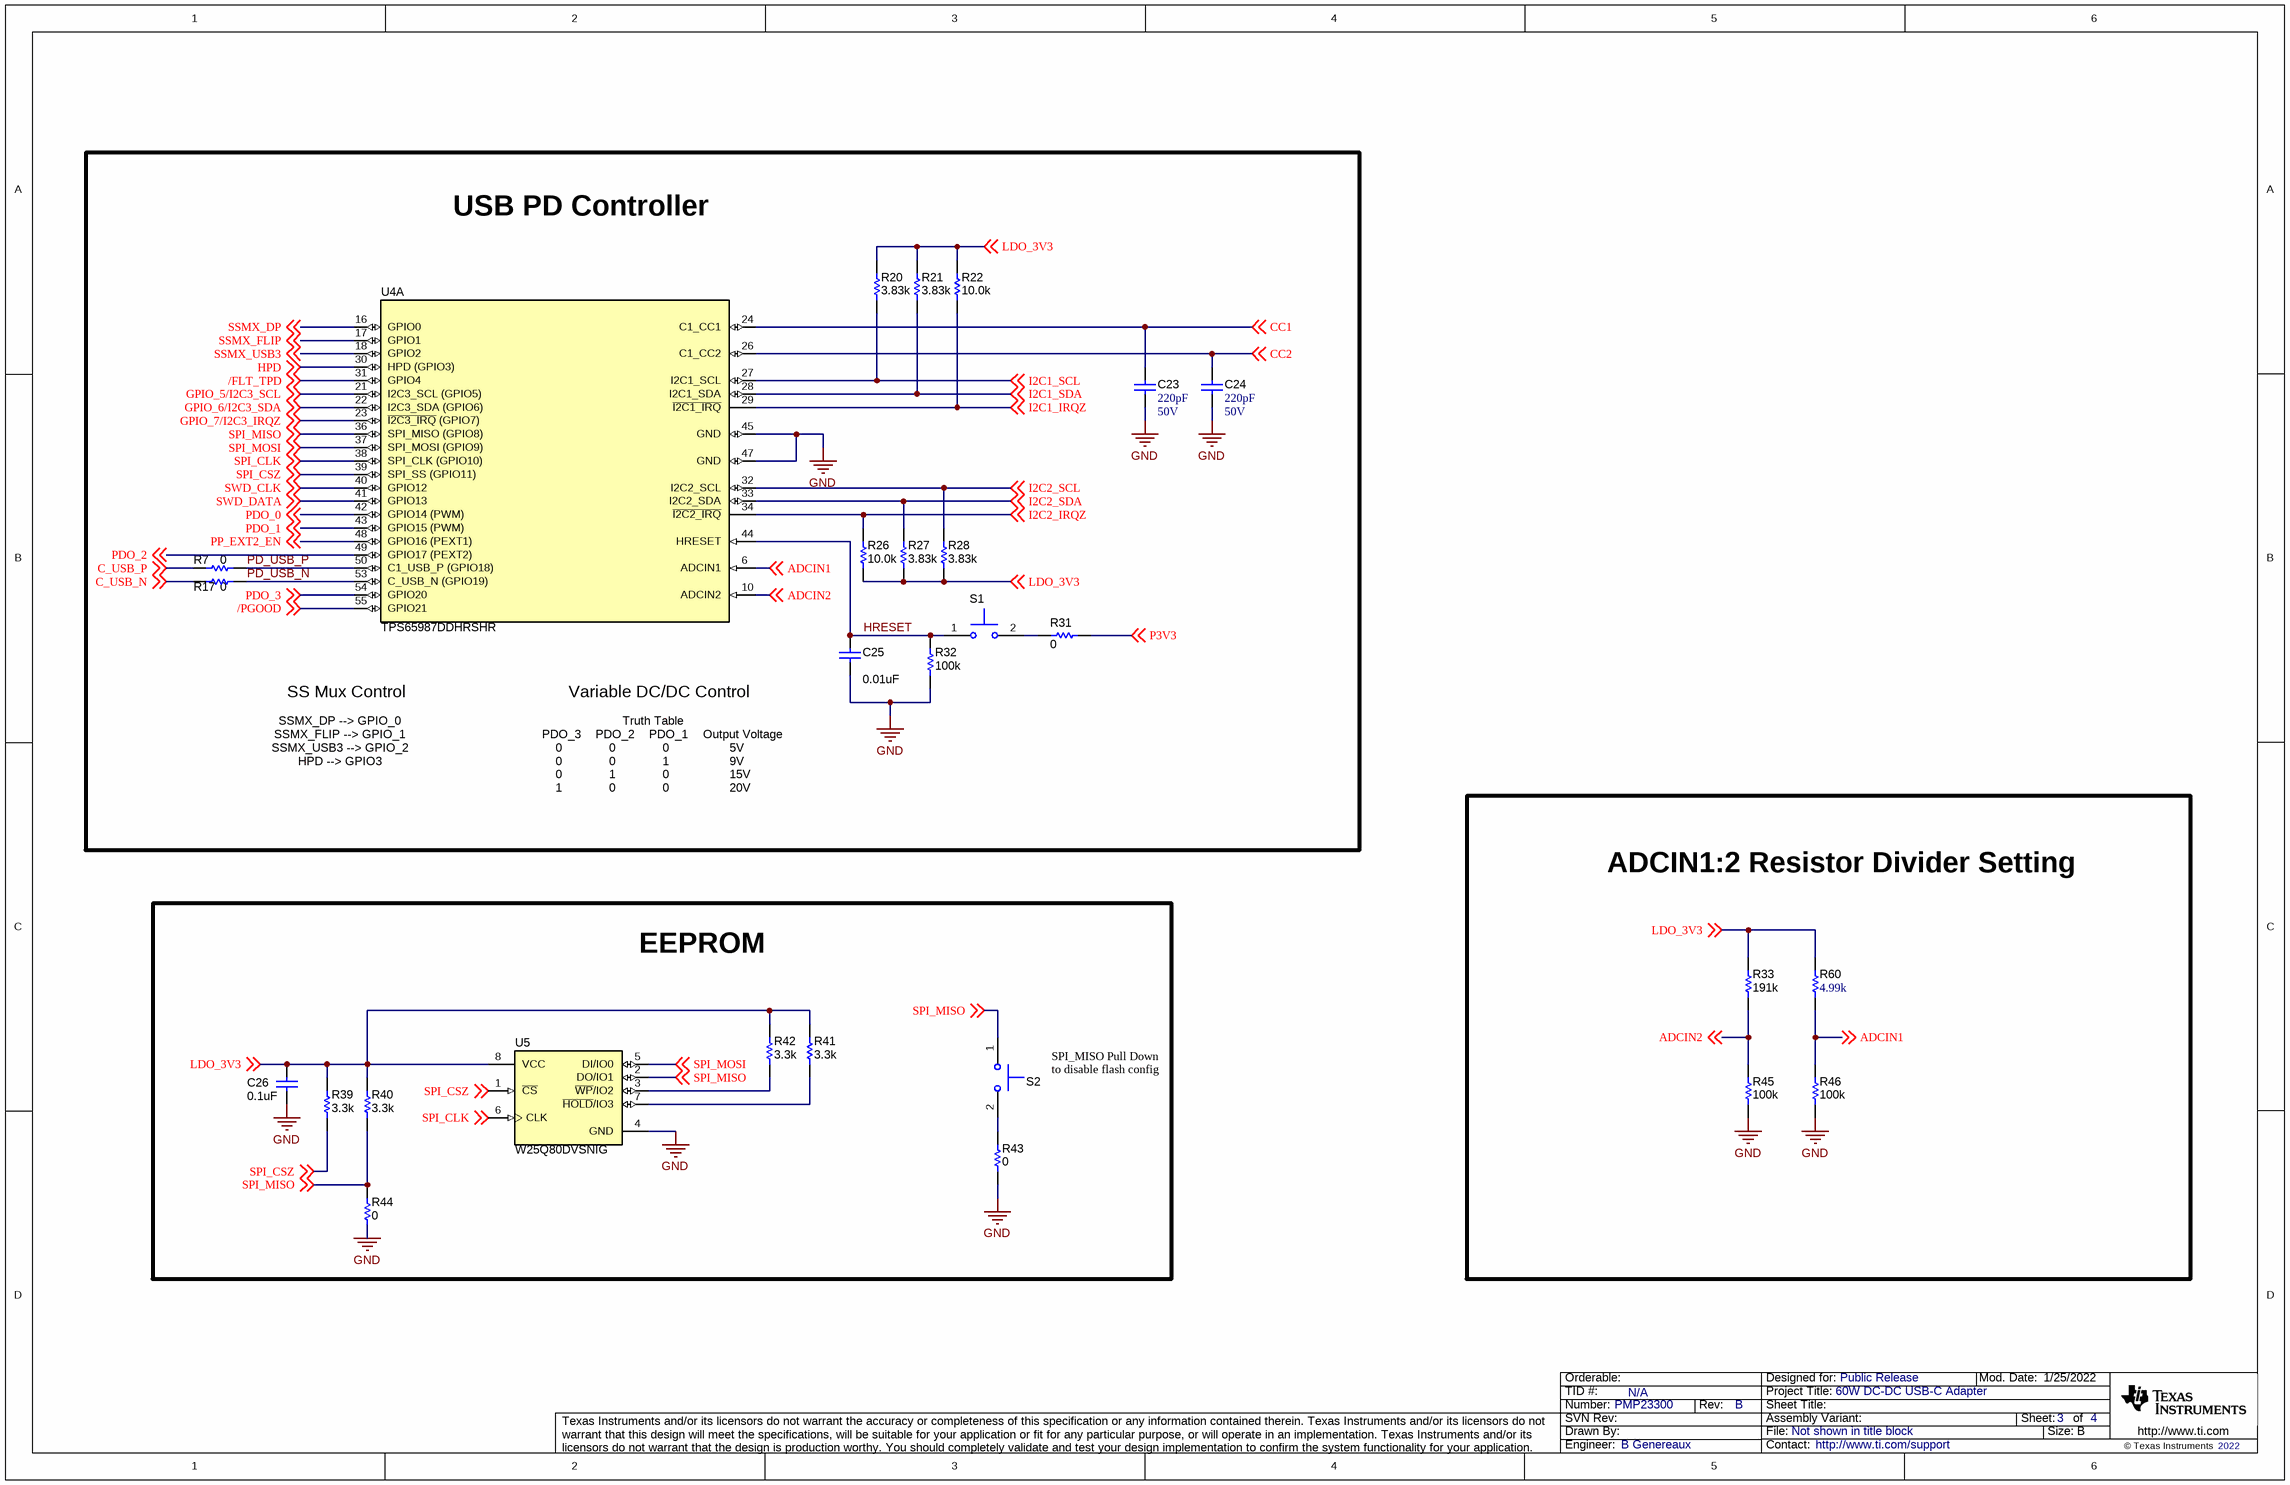
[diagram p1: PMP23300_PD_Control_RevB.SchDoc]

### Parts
C23  ValueDisplayed: 220pF  VDC_V: 50V  [0402]  (hidden comment: CC0402KRX7R9BB221)
C24  ValueDisplayed: 220pF  VDC_V: 50V  [0402]  (hidden comment: CC0402KRX7R9BB221)
C25  ValueDisplayed: 0.01uF  [0402]  (hidden comment: GCM155R71H103KA55D)
C26  ValueDisplayed: 0.1uF  [0402]  (hidden comment: 885012205037)
R7  ValueDisplayed: 0  [0402]  (hidden comment: RC0402JR-070RL)
R17  ValueDisplayed: 0  [0402]  (hidden comment: RC0402JR-070RL)
R20  ValueDisplayed: 3.83k  [0402]  (hidden comment: CRCW04023K83FKED)
R21  ValueDisplayed: 3.83k  [0402]  (hidden comment: CRCW04023K83FKED)
R22  ValueDisplayed: 10.0k  [0402]  (hidden comment: ERJ-2RKF1002X)
R26  ValueDisplayed: 10.0k  [0402]  (hidden comment: ERJ-2RKF1002X)
R27  ValueDisplayed: 3.83k  [0402]  (hidden comment: CRCW04023K83FKED)
R28  ValueDisplayed: 3.83k  [0402]  (hidden comment: CRCW04023K83FKED)
R31  ValueDisplayed: 0  [0402]  (hidden comment: RC0402JR-070RL)
R32  ValueDisplayed: 100k  [0402]  (hidden comment: CRCW0402100KFKED)
R33  ValueDisplayed: 191k  [0402]  (hidden comment: CRCW0402191KFKED)
R39  ValueDisplayed: 3.3k  [0402]  (hidden comment: CRCW04023K30JNED)
R40  ValueDisplayed: 3.3k  [0402]  (hidden comment: CRCW04023K30JNED)
R41  ValueDisplayed: 3.3k  [0402]  (hidden comment: CRCW04023K30JNED)
R42  ValueDisplayed: 3.3k  [0402]  (hidden comment: CRCW04023K30JNED)
R43  ValueDisplayed: 0  [0402]  (hidden comment: RC0402JR-070RL)
R44  ValueDisplayed: 0  [0402]  (hidden comment: RC0402JR-070RL)
R45  ValueDisplayed: 100k  [0402]  (hidden comment: CRCW0402100KFKED)
R46  ValueDisplayed: 100k  [0402]  (hidden comment: CRCW0402100KFKED)
R60  ValueDisplayed: 4.99k  [0402]  (hidden comment: RC0402FR-074K99L)
S1  B3U-1000P  [SW_B3U-1000P]  (value not drawn)
S2  B3U-1000P  [SW_B3U-1000P]  (value not drawn)
U4  TPS65987DDHRSHR  [RSH0056E]  (part A of 2)
U5  W25Q80DVSNIG  [SOIC-8]

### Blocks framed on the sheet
USB PD Controller: C23-C25 R7 R17 R20-R22 R26-R28 R31 R32 S1 U4
ADCIN1:2 Resistor Divider Setting: R33 R45 R46 R60
EEPROM: C26 R39-R44 S2 U5

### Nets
GND: C23.2 C24.2 C25.2 C26.2 R32.1 R43.1 R44.1 R45.1 R46.1 U4.45(GND) U4.47(GND) U5.4(GND)
/FLT_TPD: U4.31(GPIO4) ; off-sheet /FLT_TPD
/PGOOD: U4.55(GPIO21) ; off-sheet /PGOOD
ADCIN1: R46.2 R60.1 U4.6(ADCIN1) ; off-sheet ADCIN1
ADCIN2: R33.1 R45.2 U4.10(ADCIN2) ; off-sheet ADCIN2
C_USB_N: R17.2 ; off-sheet C_USB_N
C_USB_P: R7.2 ; off-sheet C_USB_P
CC1: C23.1 U4.24(C1_CC1) ; off-sheet CC1
CC2: C24.1 U4.26(C1_CC2) ; off-sheet CC2
GPIO_5/I2C3_SCL: U4.21(I2C3_SCL_(GPIO5)) ; off-sheet GPIO_5/I2C3_SCL
GPIO_6/I2C3_SDA: U4.22(I2C3_SDA_(GPIO6)) ; off-sheet GPIO_6/I2C3_SDA
GPIO_7/I2C3_IRQZ: U4.23(~{I2C3_IRQ}_(GPIO7)) ; off-sheet GPIO_7/I2C3_IRQZ
HPD: U4.30(HPD_(GPIO3)) ; off-sheet HPD
HRESET: C25.1 R32.2 S1.1 U4.44(HRESET)
I2C1_IRQZ: R22.2 U4.29(~{I2C1_IRQ}) ; off-sheet I2C1_IRQZ
I2C1_SCL: R20.2 U4.27(I2C1_SCL) ; off-sheet I2C1_SCL
I2C1_SDA: R21.2 U4.28(I2C1_SDA) ; off-sheet I2C1_SDA
I2C2_IRQZ: R26.2 U4.34(~{I2C2_IRQ}) ; off-sheet I2C2_IRQZ
I2C2_SCL: R28.2 U4.32(I2C2_SCL) ; off-sheet I2C2_SCL
I2C2_SDA: R27.2 U4.33(I2C2_SDA) ; off-sheet I2C2_SDA
LDO_3V3: C26.1 R20.1 R21.1 R22.1 R26.1 R27.1 R28.1 R33.2 R39.1 R40.1 R41.2 R42.1 R60.2 U5.8(VCC) ; off-sheet LDO_3V3
P3V3: R31.2 ; off-sheet P3V3
PD_USB_N: R17.1 U4.53(C_USB_N_(GPIO19))
PD_USB_P: R7.1 U4.50(C1_USB_P_(GPIO18))
PDO_0: U4.42(GPIO14_(PWM)) ; off-sheet PDO_0
PDO_1: U4.43(GPIO15_(PWM)) ; off-sheet PDO_1
PDO_2: U4.49(GPIO17_(PEXT2)) ; off-sheet PDO_2
PDO_3: U4.54(GPIO20) ; off-sheet PDO_3
PP_EXT2_EN: U4.48(GPIO16_(PEXT1)) ; off-sheet PP_EXT2_EN
SPI_CLK: U4.38(SPI_CLK_(GPIO10)) U5.6(CLK) ; off-sheet SPI_CLK
SPI_CSZ: R39.2 U4.39(SPI_SS_(GPIO11)) U5.1(~{CS}) ; off-sheet SPI_CSZ
SPI_MISO: R40.2 R44.2 S2.1 U4.36(SPI_MISO_(GPIO8)) U5.2(DO/IO1) ; off-sheet SPI_MISO
SPI_MOSI: U4.37(SPI_MOSI_(GPIO9)) U5.5(DI/IO0) ; off-sheet SPI_MOSI
SSMX_DP: U4.16(GPIO0) ; off-sheet SSMX_DP
SSMX_FLIP: U4.17(GPIO1) ; off-sheet SSMX_FLIP
SSMX_USB3: U4.18(GPIO2) ; off-sheet SSMX_USB3
SWD_CLK: U4.40(GPIO12) ; off-sheet SWD_CLK
SWD_DATA: U4.41(GPIO13) ; off-sheet SWD_DATA
NetR31_1: R31.1 S1.2
NetR41_1: R41.1 U5.7(~{HOLD}/IO3)
NetR42_2: R42.2 U5.3(~{WP}/IO2)
NetR43_2: R43.2 S2.2

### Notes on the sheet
- SS Mux Control
- Variable DC/DC Control
- SSMX_USB3 --> GPIO_2
- SSMX_FLIP --> GPIO_1
- SSMX_DP --> GPIO_0
- HPD --> GPIO3
- PDO_3
- 0
- PDO_2
- Truth Table
- PDO_1
- 1
- Output Voltage
- 5V
- 9V
- 15V
- 20V
- SPI_MISO Pull Down
- to disable flash config

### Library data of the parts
C23 C24 = CMP-0860558-1: CAP, CERM, 220 pF, 50 V,+/- 10%, X7R, 0402; Manufacturer: Yageo; SizeAreaWB_mm2: 3; SizeZ_mm: 0.6; Value: 220pF; TaMax_C: 125°C; U/M: EA; AEC Category: Q200; SizeX_mm: 1; AEC Qualified: N; TaMin_C: -55°C; SizeArea_mm2: 0.5
C25 = CMP-0006355-1: CAP, CERM, 0.01 uF, 50 V, +/- 10%, C0G/NP0, 0402; Manufacturer: MuRata; TaMin_C: -55°C; Polarized: N; SizeAreaWB_mm2: 3; Value1: Unknown; U/M: EA; Value: 0.01uF; TaMax_C: 125°C; SizeZ_mm: 0.6; SizeX_mm: 1; SizeY_mm: 0.5; Value2: 50V; Cap_F: 10nF; AEC Category: Q200
C26 = CMP-0006228-2: CAP, CERM, 0.1 uF, 16 V, +/- 10%, X7R, 0402; Manufacturer: Wurth Elektronik; Polarized: N; Value: 0.1uF; U/M: EA; Cap_F: 100nF; Value1: Unknown; VDC_V: 16V; TaMin_C: -55°C; TaMax_C: 125°C; SizeArea_mm2: 0.5; SizeAreaWB_mm2: 3; SizeX_mm: 1; SizeZ_mm: 0.6; AEC Category: Q200
R7 R17 R31 R43 R44 = CMP-0027004-2: RES, 0, 5%, 0.063 W, 0402; Manufacturer: Yageo America; Value: 0; Value_Code: 0000; Power_W: 63mW; Value2: 0.063W; VDC_V: 50V; TempCo: 200 ppm/C; SizeArea_mm2: 0.5; SizeX_mm: 1; SizeZ_mm: 0.6; EIA_Code: E24; U/M: EA; AEC Category: Q200
R20 R28 = CMP-0026339-2: RES, 3.83 k, 1%, 0.063 W, AEC-Q200 Grade 0, 0402; Manufacturer: Vishay-Dale; Value: 3.83k; Value_Code: 3k83; Power_W: 63mW; Value2: 0.063W; VDC_V: 50V; TempCo: 100 ppm/C; SizeArea_mm2: 0.5; SizeX_mm: 1; SizeZ_mm: 0.6; EIA_Code: E96; AEC Category: Q200; AEC Qualified: Y; AEC Grade: 0
R21 R27 = CMP-0026339-2: RES, 3.83 k, 1%, 0.063 W, AEC-Q200 Grade 0, 0402; Manufacturer: Vishay-Dale; Power_W: 63mW; TempCo: 100 ppm/C; Value_Code: 3k83; Value: 3.83k; EIA_Code: E96; SizeX_mm: 1; SizeY_mm: 0.5; SizeZ_mm: 0.6; Value2: 0.063W; CompType: Resistor; AEC Qualified: Y; VDC_V: 50V; AEC Category: Q200; AEC Grade: 0
R22 R26 = CMP-0026658-1: as R35 on sheet PMP23300_DC-DC_RevB
R32 R45 R46 = CMP-0025950-3: RES, 100 k, 1%, 0.063 W, AEC-Q200 Grade 0, 0402; Manufacturer: Vishay-Dale; Value: 100k; Power_W: 63mW; Value2: 0.063W; VDC_V: 50V; TempCo: 100 ppm/C; SizeArea_mm2: 0.5; SizeX_mm: 1; SizeZ_mm: 0.6; EIA_Code: E96; AEC Category: Q200; AEC Qualified: Y; AEC Grade: 0
R33 = CMP-0026063-3: RES, 191 k, 1%, 0.063 W, AEC-Q200 Grade 0, 0402; Manufacturer: Vishay-Dale; Value: 191k; Power_W: 63mW; Value2: 0.063W; VDC_V: 50V; TempCo: 100 ppm/C; SizeArea_mm2: 0.5; SizeX_mm: 1; SizeZ_mm: 0.6; EIA_Code: E96; AEC Category: Q200; AEC Qualified: Y; AEC Grade: 0
R39-R42 = CMP-0026918-5: RES, 3.3 k, 5%, 0.063 W, AEC-Q200 Grade 0, 0402; Manufacturer: Vishay-Dale; Value: 3.3k; Value_Code: 3k30; Power_W: 63mW; Value2: 0.063W; VDC_V: 50V; TempCo: 200 ppm/C; EIA_Code: E24; AEC Category: Q200; AEC Grade: 0; AEC Qualified: Y; SizeArea_mm2: 0.5; SizeX_mm: 1; SizeZ_mm: 0.6
R60 = CMP-0026740-1: as R69 on sheet PMP23300_DC-DC_RevB
S1 S2 = CMP-0002150-2: SWITCH TACTILE SPST-NO 0.05A 12V; Manufacturer: Omron Electronic Components; SwitchFunction: Off-Mom; PositionCount: 1; CurrentRating_mA: 50A
U4 = CMP-0081032-2: USB Type-C and USB PD Controller with Integrated Power Switches, RSH0056E (VQFN-56); Alternate PartNumber: TPS65987DDHRSHT; Alternate Manufacturer: Texas Instruments; SizeAreaWB_mm2: 81; SizeZ_mm: 1; SizeX_mm: 7; SizeArea_mm2: 49; CompType: IC; AEC Qualified: N; AEC Category: Q200
U5 = CMP-0005376-2: 3V, 8Mbit, Serial Flash Memory with Dual and Qual SPI, SOIC-8; Manufacturer: Winbond; SizeZ_mm: 1.75; SizeX_mm: 5.99; SizeY_mm: 4.9; SizeArea_mm2: 29.351; SizeAreaWB_mm2: 55.131

## Sheet PMP23300_TIVA_RevB.SchDoc
size 431 x 279 mm; Date: Not shown in title block; ApprovedBy: Not shown in title block; CheckedBy: Not shown in title block; Author: Not shown in title block; CompanyName: Not shown in title block; Engineer: Not shown in title block; Organization: Not shown in title block; Address1: Not shown in title block; Address2: Not shown in title block; Address3: Not shown in title block; Address4: Not shown in title block; DocumentNumber: 4; Revision: Use project parameter SCH_Rev; SheetNumber: 4; SheetTotal: 4; PageSetup: Record=PageOptions¦CenterHorizontal=True¦CenterVertical=True¦PrintScale=1.00¦XCorrection=1.00¦YCorrection=1.00¦PrintKind=0¦BorderSize=5000000¦LeftOffset=0¦BottomOffset=0¦Orientation=2¦PaperLength=1000¦PaperWidth=1000¦Scale=100¦PaperSource=15¦PrintQuality=600¦MediaType=1¦DitherType=10¦PaperKind=Letter¦PrintScaleMode=1
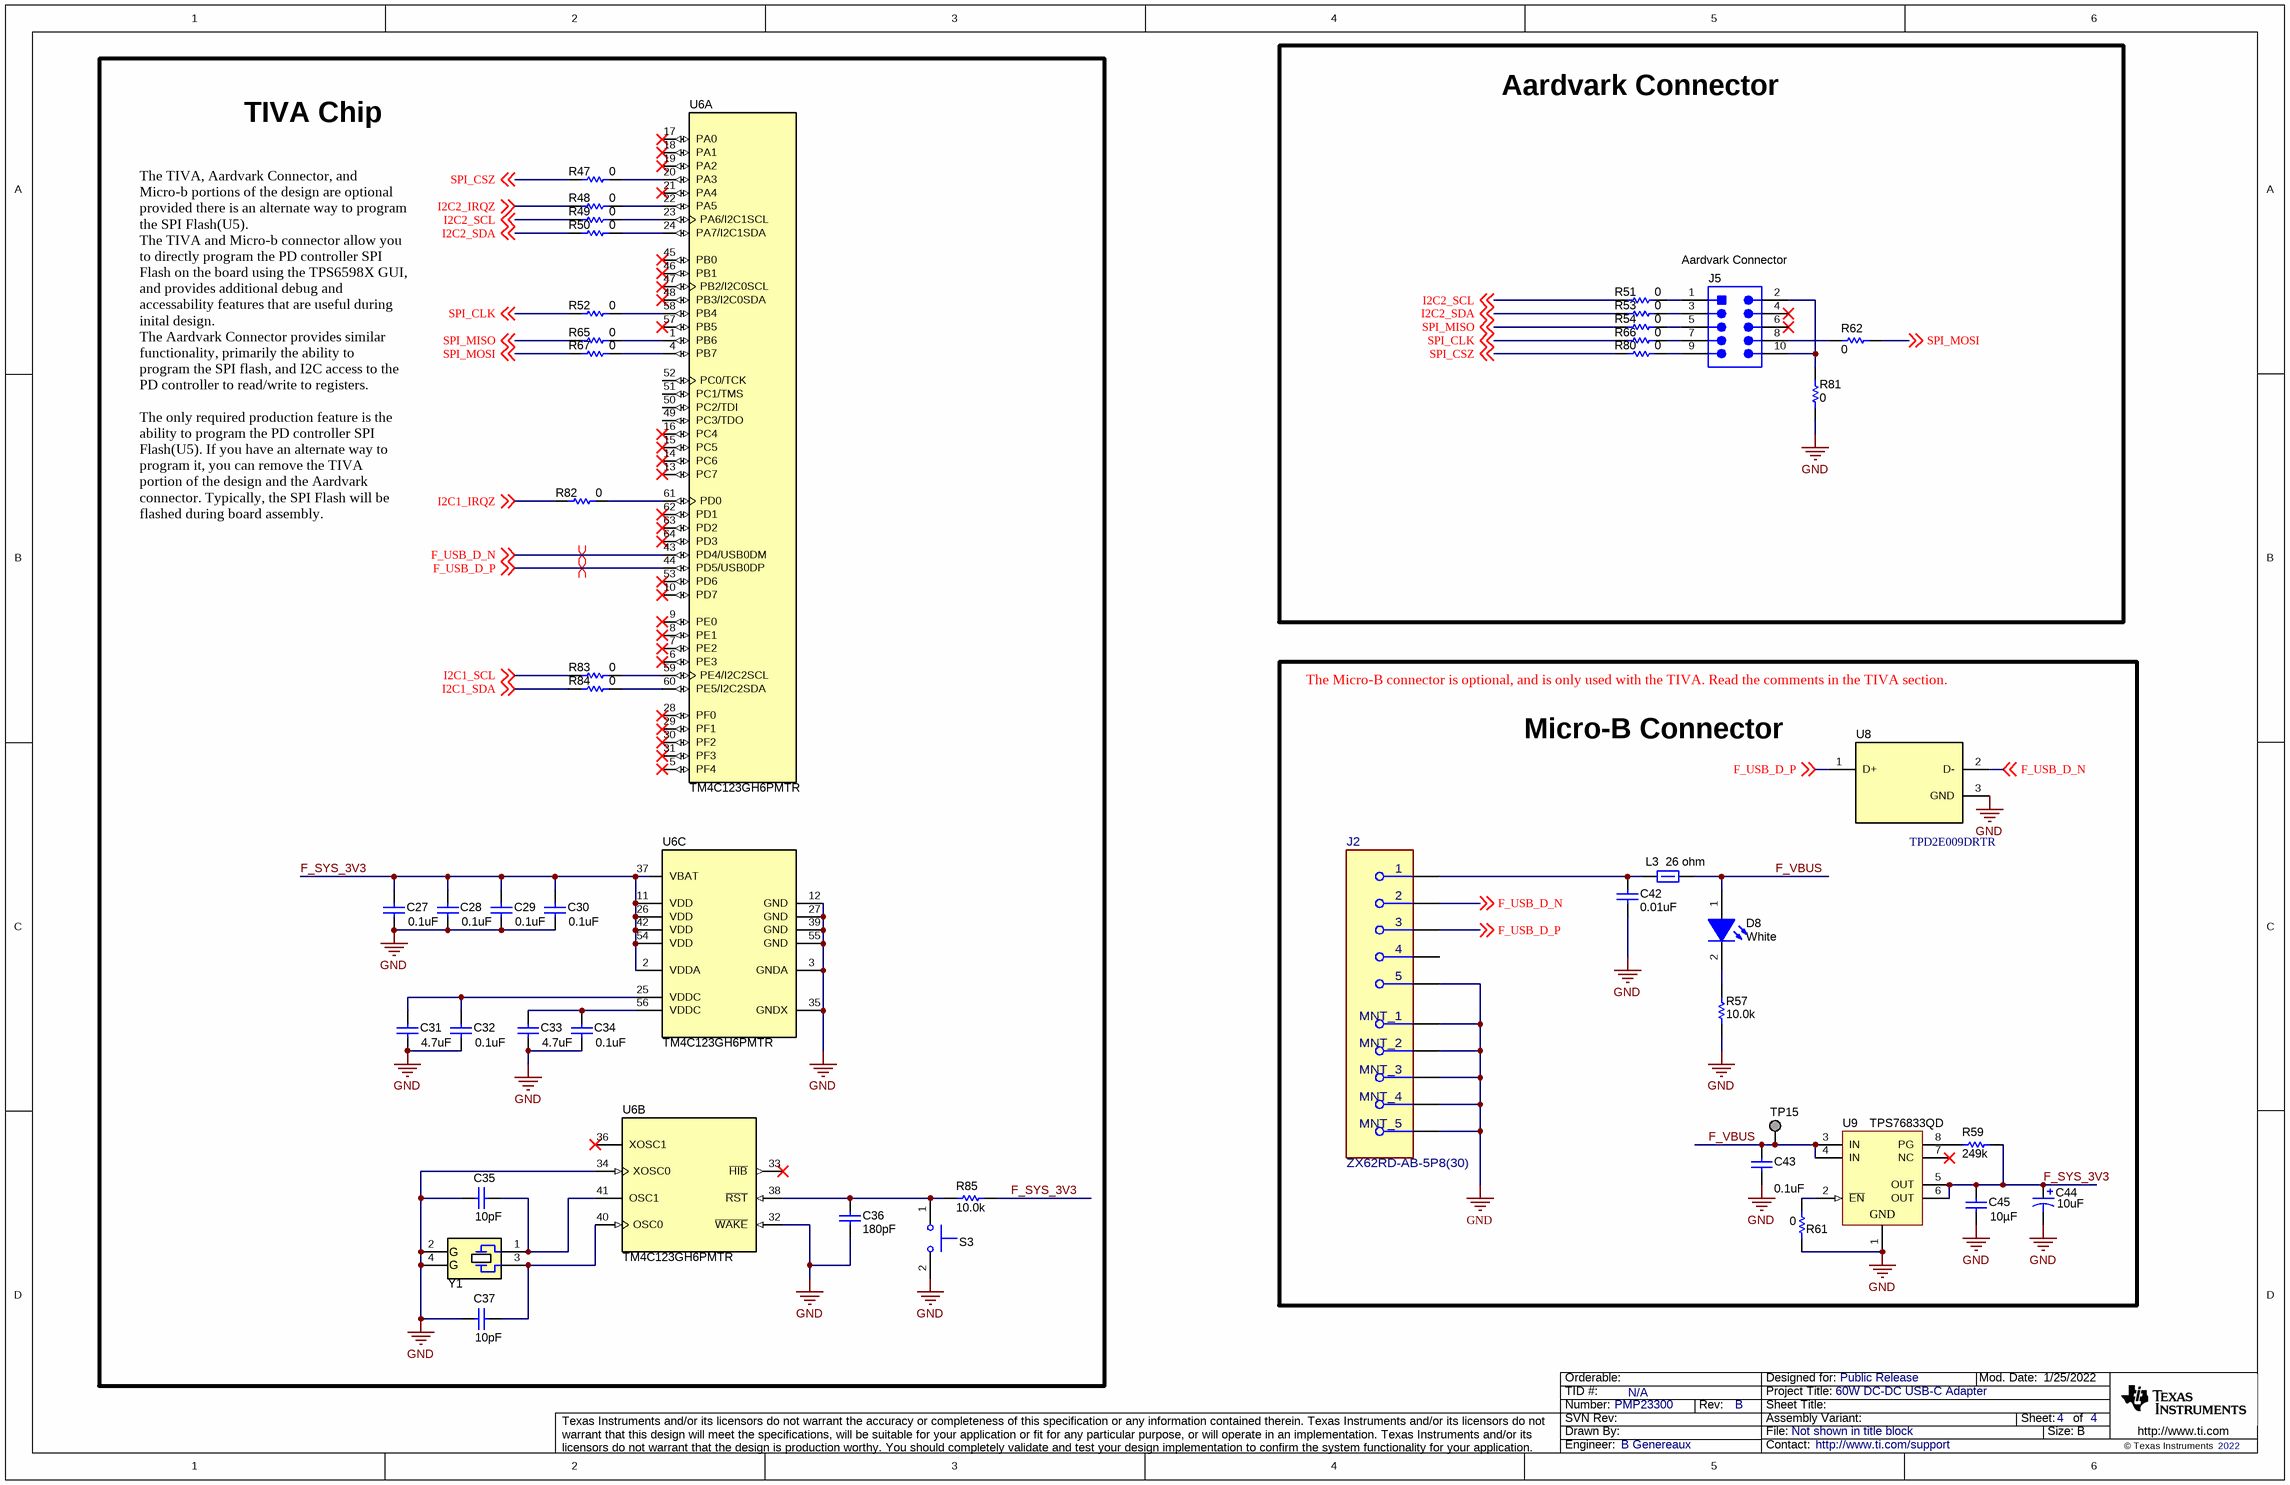
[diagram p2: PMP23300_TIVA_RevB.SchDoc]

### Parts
C27  ValueDisplayed: 0.1uF  [0402]  (hidden comment: GCM155R71H104KE02D)
C28  ValueDisplayed: 0.1uF  [0402]  (hidden comment: GCM155R71H104KE02D)
C29  ValueDisplayed: 0.1uF  [0402]  (hidden comment: GCM155R71H104KE02D)
C30  ValueDisplayed: 0.1uF  [0402]  (hidden comment: GCM155R71H104KE02D)
C31  ValueDisplayed: 4.7uF  [0402]  (hidden comment: C1005X5R1A475M050BC)
C32  ValueDisplayed: 0.1uF  [0402]  (hidden comment: GCM155R71H104KE02D)
C33  ValueDisplayed: 4.7uF  [0402]  (hidden comment: C1005X5R1A475M050BC)
C34  ValueDisplayed: 0.1uF  [0402]  (hidden comment: GCM155R71H104KE02D)
C35  ValueDisplayed: 10pF  [0603]  (hidden comment: CGA3E2C0G1H100D080AA)
C36  ValueDisplayed: 180pF  [0603]  (hidden comment: 06035A181JAT2A)
C37  ValueDisplayed: 10pF  [0603]  (hidden comment: CGA3E2C0G1H100D080AA)
C42  ValueDisplayed: 0.01uF  [0402]  (hidden comment: C0402C103J5RACTU)
C43  ValueDisplayed: 0.1uF  [0402]  (hidden comment: GCM155R71H104KE02D)
C44  ValueDisplayed: 10uF  [3528-21]  (hidden comment: 293D106X9010B2TE3)
C45  ValueDisplayed: 10µF  [0402_080]  (hidden comment: 0402ZD106MAT2A)
D8  value White  [LW QH8G_White]  (hidden comment: LW QH8G-Q2S2-3K5L-1)
J2  ZX62RD-AB-5P8(30)  [FP-ZX62RD-AB-5P8(30)_CONN_USB-MFG]
J5  PEC05DAAN  [CONN_PEC05DAAN]  (value not drawn)
L3  value 26 ohm  [0603]  (hidden comment: BLM18SG260TN1D)
R47  ValueDisplayed: 0  [0402]  (hidden comment: RC0402JR-070RL)
R48  ValueDisplayed: 0  [0402]  (hidden comment: RC0402JR-070RL)
R49  ValueDisplayed: 0  [0402]  (hidden comment: RC0402JR-070RL)
R50  ValueDisplayed: 0  [0402]  (hidden comment: RC0402JR-070RL)
R51  ValueDisplayed: 0  [0402]  (hidden comment: RC0402JR-070RL)
R52  ValueDisplayed: 0  [0402]  (hidden comment: RC0402JR-070RL)
R53  ValueDisplayed: 0  [0402]  (hidden comment: RC0402JR-070RL)
R54  ValueDisplayed: 0  [0402]  (hidden comment: RC0402JR-070RL)
R57  ValueDisplayed: 10.0k  [0402]  (hidden comment: ERJ-2RKF1002X)
R59  ValueDisplayed: 249k  [0603]  (hidden comment: CRCW0603249KFKEA)
R61  ValueDisplayed: 0  [0402]  (hidden comment: CRCW04020000Z0ED)
R62  ValueDisplayed: 0  [0402]  (hidden comment: RC0402JR-070RL)
R65  ValueDisplayed: 0  [0402]  (hidden comment: RC0402JR-070RL)
R66  ValueDisplayed: 0  [0402]  (hidden comment: RC0402JR-070RL)
R67  ValueDisplayed: 0  [0402]  (hidden comment: RC0402JR-070RL)
R80  ValueDisplayed: 0  [0402]  (hidden comment: RC0402JR-070RL)
R81  ValueDisplayed: 0  [0402]  (hidden comment: RC0402JR-070RL)
R82  ValueDisplayed: 0  [0402]  (hidden comment: RC0402JR-070RL)
R83  ValueDisplayed: 0  [0402]  (hidden comment: RC0402JR-070RL)
R84  ValueDisplayed: 0  [0402]  (hidden comment: RC0402JR-070RL)
R85  ValueDisplayed: 10.0k  [0402]  (hidden comment: CRCW040210K0FKED)
S3  B3U-1000P  [SW_B3U-1000P]  (value not drawn)
TP15  S1751-46  [Harwin_S1751-46]  (value not drawn)
U6  TM4C123GH6PMTR  [PM0064A_L]  (parts A,B,C of 3)
U8  TPD2E009DRTR  [DRT0003A]
U9  TPS76833QD  [D0008A_N]
Y1  NX3225GA-16.000M-STD-CRG-1  [NDK_NX3225GA]  (value not drawn)

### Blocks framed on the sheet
Aardvark Connector: J5 R51 R53 R54 R62 R66 R80 R81
TIVA Chip: C27-C37 R47-R50 R52 R65 R67 R82-R85 S3 U6 Y1
Micro-B Connector: C42-C45 D8 J2 L3 R57 R59 R61 TP15 U8 U9

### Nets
GND: C27.2 C28.2 C29.2 C30.2 C31.2 C32.1 C33.2 C34.1 C35.1 C36.1 C37.1 C42.2 C43.2 C44.2(-) C45.2 J2.5 J2.6(MNT_1) J2.7(MNT_2) J2.8(MNT_3) J2.9(MNT_4) J2.10(MNT_5) R57.1 R61.2 R81.2 S3.2 U6.3(GNDA) U6.12(GND) U6.27(GND) U6.32(~{WAKE}) U6.34(XOSC0) U6.35(GNDX) U6.39(GND) U6.55(GND) U8.3(GND) U9.1(GND) Y1.2(GND) Y1.4(GND)
F_SYS_3V3: C27.1 C28.1 C29.1 C30.1 C44.1(+) C45.1 R59.2 R85.1 U6.2(VDDA) U6.11(VDD) U6.26(VDD) U6.37(VBAT) U6.42(VDD) U6.54(VDD) U9.5(OUT) U9.6(OUT)
F_USB_D_N: J2.2 U6.43(PD4/USB0DM) U8.2(D-) ; off-sheet F_USB_D_N
F_USB_D_P: J2.3 U6.44(PD5/USB0DP) U8.1(D+) ; off-sheet F_USB_D_P
F_VBUS: C43.1 D8.1(A) L3.2 TP15.1 U9.3(IN) U9.4(IN)
I2C1_IRQZ: R82.2 ; off-sheet I2C1_IRQZ
I2C1_SCL: R83.2 ; off-sheet I2C1_SCL
I2C1_SDA: R84.2 ; off-sheet I2C1_SDA
I2C2_IRQZ: R48.2 ; off-sheet I2C2_IRQZ
I2C2_SCL: R49.2 R51.2 ; off-sheet I2C2_SCL
I2C2_SDA: R50.2 R53.2 ; off-sheet I2C2_SDA
SPI_CLK: R52.2 R66.2 ; off-sheet SPI_CLK
SPI_CSZ: R47.2 R80.2 ; off-sheet SPI_CSZ
SPI_MISO: R54.2 R65.2 ; off-sheet SPI_MISO
SPI_MOSI: R62.1 R67.2 ; off-sheet SPI_MOSI
NetC31_1: C31.1 C32.2 U6.25(VDDC)
NetC33_1: C33.1 C34.2 U6.56(VDDC)
NetC35_2: C35.2 U6.41(OSC1) Y1.1
NetC36_2: C36.2 R85.2 S3.1 U6.38(~{RST})
NetC37_2: C37.2 U6.40(OSC0) Y1.3
NetC42_1: C42.1 J2.1 L3.1
NetD8_2: D8.2(K) R57.2
NetJ5_1: J5.1 R51.1
NetJ5_2: J5.2 J5.10 R81.1
NetJ5_3: J5.3 R53.1
NetJ5_5: J5.5 R54.1
NetJ5_7: J5.7 R66.1
NetJ5_8: J5.8 R62.2
NetJ5_9: J5.9 R80.1
NetR47_1: R47.1 U6.20(PA3)
NetR48_1: R48.1 U6.22(PA5)
NetR49_1: R49.1 U6.23(PA6/I2C1SCL)
NetR50_1: R50.1 U6.24(PA7/I2C1SDA)
NetR52_1: R52.1 U6.58(PB4)
NetR59_1: R59.1 U9.8(PG)
NetR61_1: R61.1 U9.2(~{EN})
NetR65_1: R65.1 U6.1(PB6)
NetR67_1: R67.1 U6.4(PB7)
NetR82_1: R82.1 U6.61(PD0)
NetR83_1: R83.1 U6.59(PE4/I2C2SCL)
NetR84_1: R84.1 U6.60(PE5/I2C2SDA)

Not connected (* = marked no-connect by the designer): J2 4; J5 4* 6*; U6 5(PF4)* 6(PE3)* 7(PE2)* 8(PE1)* 9(PE0)* 10(PD7)* 13(PC7)* 14(PC6)* 15(PC5)* 16(PC4)* 17(PA0)* 18(PA1)* 19(PA2)* 21(PA4)* 28(PF0)* 29(PF1)* 30(PF2)* 31(PF3)* 33(~{HIB})* 36(XOSC1)* 45(PB0)* 46(PB1)* 47(PB2/I2C0SCL)* 48(PB3/I2C0SDA)* 49(PC3/TDO) 50(PC2/TDI) 51(PC1/TMS) 52(PC0/TCK) 53(PD6)* 57(PB5)* 62(PD1)* 63(PD2)* 64(PD3)*; U9 7(NC)*

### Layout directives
differential pair: F_USB_D_N, F_USB_D_P

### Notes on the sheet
- Aardvark Connector
- The TIVA, Aardvark Connector, and Micro-b portions of the design are optional provided there is an alternate way to program the SPI Flash(U5).
  The TIVA and Micro-b connector allow you to directly program the PD controller SPI Flash on the board using the TPS6598X GUI, and provides additional debug and accessability features that are useful during inital design.
  The Aardvark Connector provides similar functionality, primarily the ability to program the SPI flash, and I2C access to the PD controller to read/write to registers.
  The only required production feature is the ability to program the PD controller SPI Flash(U5). If you have an alternate way to program it, you can remove the TIVA portion of the design and the Aardvark connector. Typically, the SPI Flash will be flashed during board assembly.
- The Micro-B connector is optional, and is only used with the TIVA. Read the comments in the TIVA section.

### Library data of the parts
C27-C30 C32 C34 C43 = CMP-0006356-2: CAP, CERM, 0.1 uF, 50 V, +/- 10%, X7R, AEC-Q200 Grade 1, 0402; Manufacturer: MuRata; TaMin_C: -55°C; Polarized: N; SizeAreaWB_mm2: 3; Value1: Unknown; U/M: EA; Value: 0.1uF; TaMax_C: 125°C; SizeZ_mm: 0.6; SizeX_mm: 1; SizeY_mm: 0.5; Value2: 50V; AEC Qualified: Y; Cap_F: 100nF; AEC Category: Q200
C31 C33 = CMP-0006269-2: CAP, CERM, 4.7 uF, 10 V, +/- 20%, X5R, 0402; Manufacturer: TDK; TaMin_C: -55°C; Polarized: N; SizeAreaWB_mm2: 3; Value1: Unknown; U/M: EA; Value: 4.7uF; TaMax_C: 85°C; SizeZ_mm: 0.6; SizeX_mm: 1; SizeY_mm: 0.5; Value2: 10V; CompType: Capacitor; Cap_F: 4.7µF; AEC Category: Q200
C35 C37 = CMP-0007069-4: CAP, CERM, 10 pF, 50 V, +/- 5%, C0G/NP0, AEC-Q200 Grade 1, 0603; Manufacturer: TDK; TaMin_C: -55°C; Polarized: N; SizeAreaWB_mm2: 4.68; Value1: Unknown; U/M: EA; Value: 10pF; TaMax_C: 125°C; SizeZ_mm: 1; SizeX_mm: 1.6; SizeY_mm: 0.8; Value2: 50V; SizeArea_mm2: 1.28; AEC Qualified: Y; AEC Category: Q200
C36 = CMP-0006770-3: CAP, CERM, 180 pF, 50 V, +/- 5%, C0G/NP0, 0603; Manufacturer: AVX; TaMin_C: -55°C; ESR_ohm: 0.09; Polarized: N; SizeAreaWB_mm2: 4.68; Value1: 0.09 ohm; U/M: EA; Value: 180pF; TaMax_C: 125°C; SizeZ_mm: 1; SizeX_mm: 1.6; SizeY_mm: 0.8; Value2: 50V; SizeArea_mm2: 1.28; AEC Category: Q200
C42 = CMP-0006236-2: CAP, CERM, 0.01 uF, 50 V, +/- 5%, X7R, 0402; Manufacturer: Kemet; Polarized: N; Value: 0.01uF; U/M: EA; Cap_F: 10nF; Value1: Unknown; VDC_V: 50V; TaMin_C: -55°C; TaMax_C: 125°C; AEC Category: Q200; SizeArea_mm2: 0.5; SizeAreaWB_mm2: 3; SizeX_mm: 1; SizeZ_mm: 0.6
C44 = CMP-0011512-2: CAP, TA, 10 uF, 10 V, +/- 10%, 2.5 ohm, SMD; Manufacturer: Vishay-Sprague; TaMin_C: -55°C; ESR_ohm: 2.5; Polarized: Y; SizeAreaWB_mm2: 17.1; Value1: 2.5 ohm; U/M: EA; Value: 10uF; TaMax_C: 125°C; SizeZ_mm: 2.1; SizeX_mm: 3.5; SizeY_mm: 2.8; Cap_Case: B; Value2: 10V; SizeArea_mm2: 9.8; CompType: Capacitor; Cap_F: 10µF; IRMS_A: 1.8dA; AEC Category: Q200
C45 = CMP-0078623-1: CAP, CERM, 10 µF, 10 V,+/- 20%, X5R, 0402; Manufacturer: AVX; TaMin_C: -55°C; Polarized: N; SizeAreaWB_mm2: 3; U/M: EA; Value: 10uF; TaMax_C: 85°C; SizeZ_mm: 0.8; SizeX_mm: 1; SizeY_mm: 0.5; Value2: 10V; AEC Category: Q200
D8 = CMP-0002919-1: as D1 on sheet PMP23300_DC-DC_RevB
J2 = CMP-0094509-1: USB - micro AB USB 2.0 Receptacle Connector 5 Position Surface Mount, Right Angle; Through Hole; Manufacturer: Hirose; ContactFinish: Gold,Nickel; Usb Standard: USB 2.0; DUT-Pitch_mm: 0.65mm; SizeZ_mm: 3.1mm; AEC Qualified: No; Current_A: 1.8A; Voltage_V: 30V; Is Female: yes
J5 = CMP-0054550-1: Header, 100mil, 5x2, Tin, TH; Manufacturer: Sullins Connector Solutions; CNHeader: TRUE; Current_A: 3A; Green_Lifecycle: Active; Shrouded: N; Gender: Male; Green_REACh: Passed; Voltage_V: 1.8kV; Row_Count: 2; RowSpacing_mm: 2.54; CT: FALSE; Cert_UL: Y
L3 = CMP-0003354-2: Ferrite Bead, 26 ohm @ 100 MHz, 6 A, 0603; Manufacturer: MuRata; Imax_A: 6A; DCR_ohm: 7m; Value1: 0.007 ohm; ZTyp@100MHz_Ohm: 26; SizeArea_mm2: 1.28; SizeAreaWB_mm2: 4.68; SizeX_mm: 1.6; SizeY_mm: 0.8; SizeZ_mm: 1
R47-R54 R62 R65-R67 R80-R84 = CMP-0027004-2: as R7 on sheet PMP23300_PD_Control_RevB
R57 = CMP-0026658-1: as R35 on sheet PMP23300_DC-DC_RevB
R59 = CMP-0022234-4: RES, 249 k, 1%, 0.1 W, AEC-Q200 Grade 0, 0603; Manufacturer: Vishay-Dale; Power_W: 100mW; TempCo: 100 ppm/C; Value: 249k; EIA_Code: E96; SizeX_mm: 1.6; SizeY_mm: 0.8; SizeZ_mm: 1; Value2: 0.1W; SizeArea_mm2: 1.28; AEC Qualified: Y; VDC_V: 75V; AEC Category: Q200; AEC Grade: 0
R61 = CMP-0026822-3: RES, 0, 5%, 0.063 W, AEC-Q200 Grade 0, 0402; Manufacturer: Vishay-Dale; Value: 0; Value_Code: 0000; Power_W: 63mW; Value2: 0.063W; VDC_V: 50V; TempCo: 200 ppm/C; SizeArea_mm2: 0.5; SizeX_mm: 1; SizeZ_mm: 0.6; EIA_Code: E24; AEC Category: Q200; AEC Qualified: Y
R85 = CMP-0025958-3: RES, 10.0 k, 1%, 0.063 W, AEC-Q200 Grade 0, 0402; Manufacturer: Vishay-Dale; Power_W: 63mW; TempCo: 100 ppm/C; Value_Code: 10k0; Value: 10.0k; EIA_Code: E96; Res_ohm: 10k; SizeX_mm: 1; SizeY_mm: 0.5; SizeZ_mm: 0.6; Value2: 0.063W; CompType: Resistor; AEC Qualified: Y; VDC_V: 50V; AEC Category: Q200; AEC Grade: 0
S3 = CMP-0002150-2: as S1 on sheet PMP23300_PD_Control_RevB
TP15 = CMP-0075188-1: as TP5 on sheet PMP23300_DC-DC_RevB
U6 = CMP-0029860-2: Tiva C Series Microcontroller, 256 KB Flash, 32 KB SRAM, 12 Bit, 12 Channels, -40 to 105 degC, 64-Pin LQFP (PM), Green (RoHS & no Sb/Br), Tape and Reel; Manufacturer: Texas Instruments; Alternate PartNumber: TM4C123GH6PMI7; Data Memory: 32 KB; I2C: 2; UART: 4; ADC Channels: 12; ADC Resolution: 12 Bit; Prefix: Qualified Device; Tiva Series: Connected MCUs; Max Speed: 80 MHz; GPIOs: 43; Program Memory: 256 KB
U8 = CMP-0043102-2: ESD Protection Array for High-Speed Data Interfaces, 2 Channels, -40 to +85 degC, 3-pin SOT (DRT), Green (RoHS & no Sb/Br); Manufacturer: Texas Instruments; Breakdown Voltage(Min)(V): 9; Differential Capacitance(pF): 0.01; IEC 61000-4-2 Air-Gap(+/- kV): 8; IO Capacitance(Typ)(pF): 0.7; IO Leakage Current(nA): 10; Serial ATA / eSATA: TRUE; SubFamily: ESD Solution
U9 = CMP-0036484-1: Single Output Fast Transient Response LDO, 1 A, Fixed 3.3 V Output, 2.7 to 10 V Input, with Low IQ, 8-pin SOIC (D), -40 to 125 degC, Green (RoHS & no Sb/Br); Manufacturer: Texas Instruments; Iout(Max)(A): 1; SubFamily: Single Channel LDO; Accuracy(%): 2; Vout Adj(Max)(V): 3.3; Power Good: TRUE; Vin(Min)(V): 2.7; Vdo(Typ)(mV): 350; Iq(Typ)(mA): 0.08; Vin(Max)(V): 10
Y1 = CMP-0004635-1: Crystal, 16 MHz, 8pF, SMD; Manufacturer: NDK; TaMax_C: 70°C; TaMin_C: -10°C; Frequency Stability: +/-30ppm; U/M: EA; Frequency_Fixed: 16MHz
